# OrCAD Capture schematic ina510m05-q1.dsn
size A; title: INA510M05-Q1 Reference Design
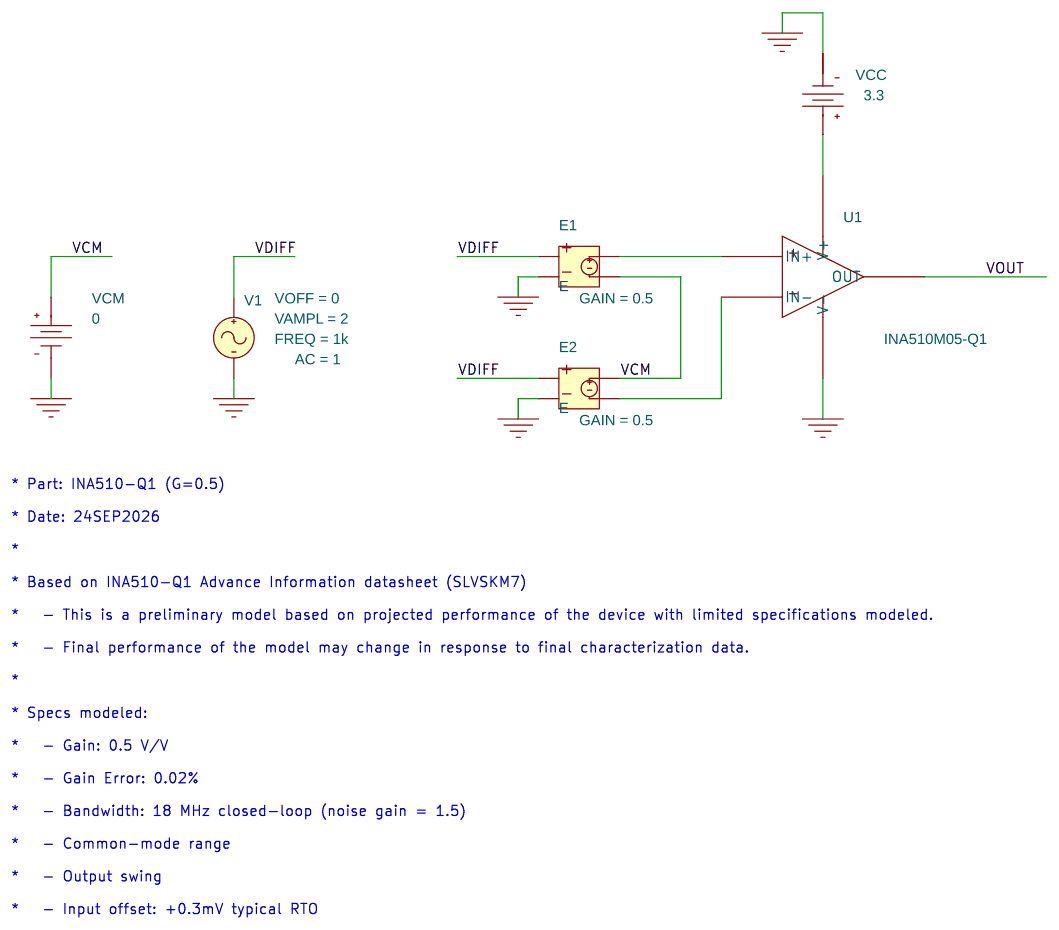
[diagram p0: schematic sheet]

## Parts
E1  E
E2  E
U1  INA510M05-Q1
V1  VSIN
VCC  VDC
VCM  VDC

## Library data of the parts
E1 E2 = E: GAIN: 0.5
U1 = INA510M05-Q1
V1 = VSIN: AC: 1; FREQ: 1k; VAMPL: 2; VOFF: 0
VCC = VDC: DC: 3.3
VCM = VDC: DC: 0

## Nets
0: E1.2 E2.2 U1.12(V-) V1.2(-) VCC.1(-) VCM.1(-)
VCM: E1.4 E2.3 VCM.0(+)
VDIFF: E1.1 E2.1 V1.1(+)
VOUT: U1.2(OUT)
N00271: E1.3 U1.5(IN+)
N00275: E2.4 U1.4(IN-)
N01817: U1.3(V+) VCC.0(+)

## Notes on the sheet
- * Part: INA510-Q1 (G=0.5)
  * Date: 24SEP2026
  *
  * Based on INA510-Q1 Advance Information datasheet (SLVSKM7)
  *   - This is a preliminary model based on projected performance of the device with limited specifications modeled.
  *   - Final performance of the model may change in response to final characterization data.
  *
  * Specs modeled:
  *   - Gain: 0.5 V/V
  *   - Gain Error: 0.02%
  *   - Bandwidth: 18 MHz closed-loop (noise gain = 1.5)
  *   - Common-mode range
  *   - Output swing
  *   - Input offset: +0.3mV typical RTO
